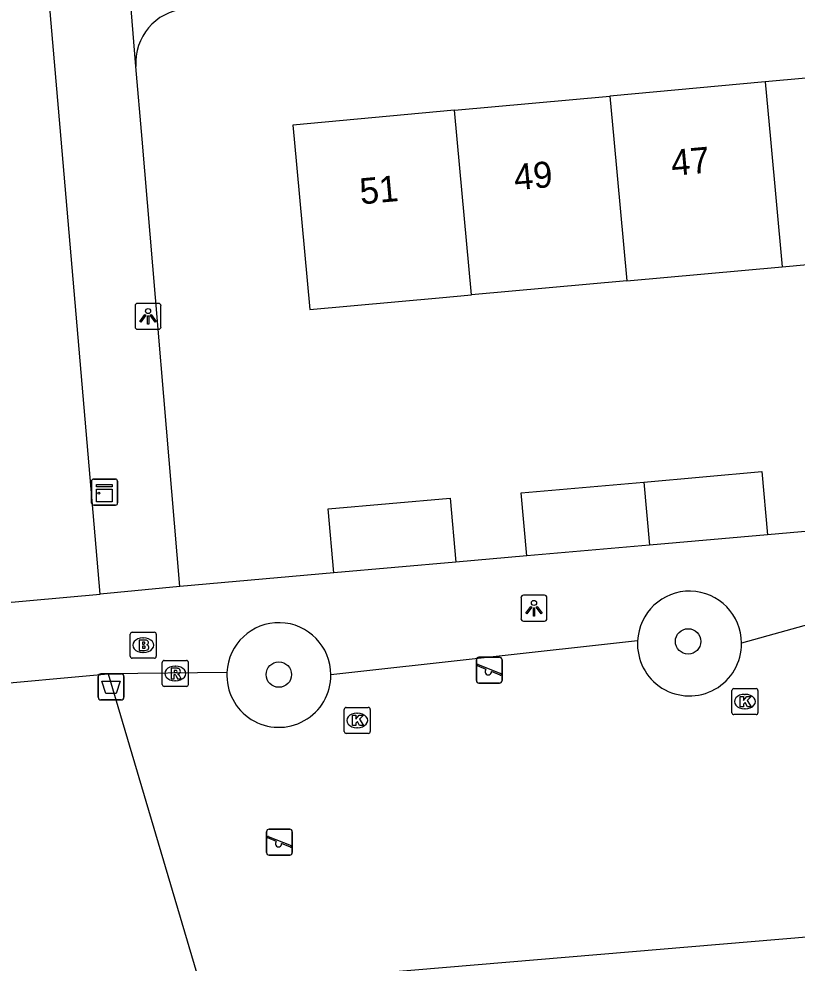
# Model space of a CAD drawing. Extents: x 160557 to 161245, y 385330 to 386505.
# Drawn here: x 160919.04 to 160948.98, y 385468.29 to 385504.63 of the extents above; entities that cross this region are included whole.
import ezdxf

# ---------------------------------------------------------------- set-up
doc = ezdxf.new("R2010")
doc.units = 0
for name, color, linetype in [('IMGEO_Afvalbak', 7, 'Continuous'), ('IMGEO_Boom', 7, 'Continuous'), ('IMGEO_Brandkraan', 7, 'Continuous'), ('IMGEO_Kast', 7, 'Continuous'), ('IMGEO_Kolk', 7, 'Continuous'), ('IMGEO_Lichtpunt', 7, 'Continuous'), ('IMGEO_Pand', 7, 'Continuous'), ('IMGEO_Pand_nummerreeks', 7, 'Continuous'), ('IMGEO_Rioolput', 7, 'Continuous'), ('IMGEO_Speelvoorziening', 7, 'Continuous'), ('IMGEO_Voetpad_open', 7, 'Continuous')]:
    doc.layers.add(name, color=color, linetype=linetype)

msp = doc.modelspace()

# ---------------------------------------------------------------- linework, layer by layer
at = {"layer": 'IMGEO_Afvalbak'}
for p, q in [((160922.086, 385478.522), (160922.086, 385479.322)), ((160922.086, 385479.322), (160922.086, 385478.522)), ((160922.186, 385479.422), (160922.976, 385479.422)), ((160922.976, 385479.422), (160922.186, 385479.422)), ((160923.076, 385479.322), (160923.076, 385478.522)), ((160923.076, 385478.522), (160923.076, 385479.322)), ((160922.976, 385478.422), (160922.186, 385478.422)), ((160922.186, 385478.422), (160922.976, 385478.422))]:
    msp.add_line(p, q, dxfattribs=at)
msp.add_lwpolyline([(160922.229, 385479.136), (160922.933, 385479.136), (160922.784, 385478.666), (160922.378, 385478.666), (160922.229, 385479.136)], dxfattribs=at)
for centre, start, end in [((160922.186, 385479.322), 90, 180), ((160922.186, 385479.322), 90, 180), ((160922.976, 385479.322), 0, 90), ((160922.976, 385479.322), 360, 90), ((160922.186, 385478.522), 180, 270), ((160922.186, 385478.522), 180, 270), ((160922.976, 385478.522), 270, 0), ((160922.976, 385478.522), 270, 0)]:
    msp.add_arc(centre, 0.1, start, end, dxfattribs=at)
at = {"layer": 'IMGEO_Boom'}
for centre in [(160944.785, 385480.673), (160929.039, 385479.396)]:
    msp.add_circle(centre, 0.489, dxfattribs=at)
at = {"layer": 'IMGEO_Brandkraan'}
for p, q in [((160923.321, 385480.099), (160923.321, 385480.951)), ((160923.396, 385481.025), (160924.248, 385481.025)), ((160923.809, 385480.805), (160923.834, 385480.805)), ((160924.322, 385480.951), (160924.322, 385480.099)), ((160923.832, 385480.245), (160923.807, 385480.245)), ((160924.248, 385480.025), (160923.396, 385480.025))]:
    msp.add_line(p, q, dxfattribs=at)
for points in [[(160923.321, 385480.099), (160923.321, 385480.951)], [(160923.396, 385481.025), (160924.248, 385481.025)], [(160924.322, 385480.951), (160924.322, 385480.099)], [(160923.669, 385480.725), (160923.669, 385480.325), (160923.882, 385480.325)], [(160923.9, 385480.725), (160923.669, 385480.725)], [(160923.848, 385480.644), (160923.794, 385480.644), (160923.794, 385480.568)], [(160923.794, 385480.568), (160923.847, 385480.568)], [(160923.856, 385480.492), (160923.794, 385480.492), (160923.794, 385480.411)], [(160923.794, 385480.411), (160923.856, 385480.411)], [(160924.248, 385480.025), (160923.396, 385480.025)]]:
    msp.add_lwpolyline(points, dxfattribs=at)
for centre, radius, start, end in [((160923.398, 385480.949), 0.0765, 91.552, 178.448), ((160923.398, 385480.949), 0.0765, 91.552, 178.448), ((160924.246, 385480.949), 0.0765, 1.552, 88.448), ((160924.246, 385480.949), 0.0765, 1.552, 88.448), ((160923.849, 385480.606), 0.0379, 267.8285, 90.9355), ((160923.857, 385480.451), 0.0404, 269.8759, 90.5077), ((160923.904, 385480.58), 0.145, 59.4692, 91.5367), ((160923.929, 385480.627), 0.0922, 285.5137, 58.1501), ((160923.934, 385480.435), 0.105, 301.3115, 78.989), ((160923.398, 385480.101), 0.0765, 181.552, 268.448), ((160923.398, 385480.101), 0.0765, 181.552, 268.448), ((160923.888, 385480.576), 0.251, 268.6676, 293.5347), ((160924.246, 385480.101), 0.0765, 271.552, 358.448), ((160924.246, 385480.101), 0.0765, 271.552, 358.448)]:
    msp.add_arc(centre, radius, start, end, dxfattribs=at)
for centre, major_axis, ratio, start_param, end_param in [((160923.808, 385480.525), (-0.387, 0.002), 0.722429, 4.712389, 7.853982), ((160923.833, 385480.525), (-0.39, 0.002), 0.717154, 1.570796, 4.712389)]:
    msp.add_ellipse(centre, major_axis=major_axis, ratio=ratio, start_param=start_param, end_param=end_param, dxfattribs=at)
at = {"layer": 'IMGEO_Kast'}
for p, q in [((160921.832, 385485.994), (160921.832, 385486.835)), ((160921.832, 385486.835), (160921.832, 385485.994)), ((160921.907, 385486.919), (160922.748, 385486.919)), ((160922.748, 385486.919), (160921.907, 385486.919)), ((160922.832, 385486.844), (160922.832, 385486.003)), ((160922.832, 385486.003), (160922.832, 385486.844)), ((160922.757, 385485.919), (160921.916, 385485.919)), ((160921.916, 385485.919), (160922.757, 385485.919))]:
    msp.add_line(p, q, dxfattribs=at)
for points in [[(160922.027, 385486.709), (160922.627, 385486.709), (160922.627, 385486.624), (160922.027, 385486.624), (160922.027, 385486.709)], [(160922.027, 385486.534), (160922.627, 385486.534), (160922.627, 385486.045), (160922.027, 385486.045), (160922.027, 385486.534)]]:
    msp.add_lwpolyline(points, dxfattribs=at)
msp.add_circle((160922.111, 385486.383), 0.0377, dxfattribs=at)
for centre, start, end in [((160921.91, 385486.841), 92.4484, 184.2845), ((160921.91, 385486.841), 92.4484, 184.2845), ((160922.754, 385486.841), 2.4484, 94.2845), ((160922.754, 385486.841), 2.4484, 94.2845), ((160921.91, 385485.997), 182.4484, 274.2845), ((160921.91, 385485.997), 182.4484, 274.2845), ((160922.754, 385485.997), 272.4484, 4.2845), ((160922.754, 385485.997), 272.4484, 4.2845)]:
    msp.add_arc(centre, 0.0779, start, end, dxfattribs=at)
at = {"layer": 'IMGEO_Kolk'}
for p, q in [((160946.471, 385477.929), (160946.471, 385478.781)), ((160946.546, 385478.855), (160947.398, 385478.855)), ((160946.959, 385478.635), (160946.984, 385478.635)), ((160947.472, 385478.781), (160947.472, 385477.929)), ((160931.554, 385477.204), (160931.554, 385478.056)), ((160931.629, 385478.13), (160932.481, 385478.13)), ((160932.042, 385477.91), (160932.067, 385477.91)), ((160932.555, 385478.056), (160932.555, 385477.204)), ((160946.982, 385478.075), (160946.957, 385478.075)), ((160947.398, 385477.855), (160946.546, 385477.855)), ((160932.065, 385477.35), (160932.04, 385477.35)), ((160932.481, 385477.13), (160931.629, 385477.13))]:
    msp.add_line(p, q, dxfattribs=at)
for points in [[(160946.471, 385477.929), (160946.471, 385478.781)], [(160946.546, 385478.855), (160947.398, 385478.855)], [(160947.472, 385478.781), (160947.472, 385477.929)], [(160946.792, 385478.555), (160946.915, 385478.555), (160946.915, 385478.404), (160947.045, 385478.555), (160947.209, 385478.555), (160947.063, 385478.404), (160947.216, 385478.155), (160947.064, 385478.155), (160946.979, 385478.319), (160946.915, 385478.252), (160946.915, 385478.155), (160946.792, 385478.155), (160946.792, 385478.555)], [(160931.554, 385477.204), (160931.554, 385478.056)], [(160931.629, 385478.13), (160932.481, 385478.13)], [(160932.555, 385478.056), (160932.555, 385477.204)], [(160931.875, 385477.83), (160931.998, 385477.83), (160931.998, 385477.679), (160932.128, 385477.83), (160932.292, 385477.83), (160932.146, 385477.679), (160932.299, 385477.43), (160932.147, 385477.43), (160932.062, 385477.594), (160931.998, 385477.527), (160931.998, 385477.43), (160931.875, 385477.43), (160931.875, 385477.83)], [(160947.398, 385477.855), (160946.546, 385477.855)], [(160932.481, 385477.13), (160931.629, 385477.13)]]:
    msp.add_lwpolyline(points, dxfattribs=at)
for centre, start, end in [((160946.548, 385478.779), 91.552, 178.448), ((160946.548, 385478.779), 91.552, 178.448), ((160947.396, 385478.779), 1.552, 88.448), ((160947.396, 385478.779), 1.552, 88.448), ((160931.631, 385478.054), 91.552, 178.448), ((160931.631, 385478.054), 91.552, 178.448), ((160932.479, 385478.054), 1.552, 88.448), ((160932.479, 385478.054), 1.552, 88.448), ((160946.548, 385477.931), 181.552, 268.448), ((160946.548, 385477.931), 181.552, 268.448), ((160947.396, 385477.931), 271.552, 358.448), ((160947.396, 385477.931), 271.552, 358.448), ((160931.631, 385477.206), 181.552, 268.448), ((160931.631, 385477.206), 181.552, 268.448), ((160932.479, 385477.206), 271.552, 358.448), ((160932.479, 385477.206), 271.552, 358.448)]:
    msp.add_arc(centre, 0.0765, start, end, dxfattribs=at)
for centre, major_axis, ratio, start_param, end_param in [((160946.958, 385478.355), (-0.387, 0.002), 0.722429, 4.712389, 7.853982), ((160946.983, 385478.355), (-0.39, 0.002), 0.717154, 1.570796, 4.712389), ((160932.041, 385477.63), (-0.387, 0.002), 0.722429, 4.712389, 7.853982), ((160932.066, 385477.63), (-0.39, 0.002), 0.717154, 1.570796, 4.712389)]:
    msp.add_ellipse(centre, major_axis=major_axis, ratio=ratio, start_param=start_param, end_param=end_param, dxfattribs=at)
at = {"layer": 'IMGEO_Lichtpunt'}
for p, q in [((160923.508, 385493.589), (160923.508, 385492.782)), ((160923.508, 385493.589), (160923.508, 385492.782)), ((160924.41, 385493.684), (160923.602, 385493.684)), ((160924.41, 385493.684), (160923.602, 385493.684)), ((160924.504, 385492.782), (160924.504, 385493.589)), ((160924.504, 385492.782), (160924.504, 385493.589)), ((160923.602, 385492.688), (160924.41, 385492.688)), ((160923.602, 385492.688), (160924.41, 385492.688)), ((160938.356, 385482.355), (160938.356, 385481.548)), ((160938.356, 385482.355), (160938.356, 385481.548)), ((160939.258, 385482.45), (160938.45, 385482.45)), ((160939.258, 385482.45), (160938.45, 385482.45)), ((160939.352, 385481.548), (160939.352, 385482.355)), ((160939.352, 385481.548), (160939.352, 385482.355)), ((160938.45, 385481.454), (160939.258, 385481.454)), ((160938.45, 385481.454), (160939.258, 385481.454))]:
    msp.add_line(p, q, dxfattribs=at)
for points in [[(160923.882, 385493.253), (160923.921, 385493.225), (160923.733, 385492.963), (160923.695, 385492.99), (160923.882, 385493.253)], [(160923.984, 385493.205), (160924.031, 385493.205), (160924.031, 385492.883), (160923.984, 385492.883), (160923.984, 385493.205)], [(160924.094, 385493.225), (160924.132, 385493.252), (160924.319, 385492.99), (160924.28, 385492.962), (160924.094, 385493.225)], [(160938.73, 385482.019), (160938.769, 385481.991), (160938.581, 385481.729), (160938.543, 385481.756), (160938.73, 385482.019)], [(160938.832, 385481.971), (160938.879, 385481.971), (160938.879, 385481.649), (160938.832, 385481.649), (160938.832, 385481.971)], [(160938.942, 385481.991), (160938.98, 385482.018), (160939.167, 385481.756), (160939.128, 385481.728), (160938.942, 385481.991)]]:
    msp.add_lwpolyline(points, dxfattribs=at)
for centre in [(160924.007, 385493.387), (160938.855, 385482.153)]:
    msp.add_circle(centre, 0.0994, dxfattribs=at)
for centre, start, end in [((160923.602, 385493.589), 90, 180), ((160923.602, 385493.589), 90, 180), ((160924.41, 385493.589), 0, 90), ((160924.41, 385493.589), 0, 90), ((160923.602, 385492.782), 180, 270), ((160923.602, 385492.782), 180, 270), ((160924.41, 385492.782), 270, 0), ((160924.41, 385492.782), 270, 360), ((160938.45, 385482.355), 90, 180), ((160938.45, 385482.355), 90, 180), ((160939.258, 385482.355), 0, 90), ((160939.258, 385482.355), 0, 90), ((160938.45, 385481.548), 180, 270), ((160938.45, 385481.548), 180, 270), ((160939.258, 385481.548), 270, 0), ((160939.258, 385481.548), 270, 360)]:
    msp.add_arc(centre, 0.0946, start, end, dxfattribs=at)
at = {"layer": 'IMGEO_Pand'}
for points in [[(160953.725, 385502.756), (160947.749, 385502.209)], [(160947.749, 385502.209), (160941.774, 385501.662)], [(160947.749, 385502.209), (160947.951, 385500), (160948.4, 385495.096)], [(160935.799, 385501.116), (160941.774, 385501.662)], [(160941.774, 385501.662), (160941.926, 385500), (160942.425, 385494.554)], [(160935.799, 385501.116), (160929.582, 385500.547), (160929.632, 385500), (160930.227, 385493.449), (160935.207, 385493.9), (160936.449, 385494.013)], [(160936.449, 385494.013), (160935.901, 385500), (160935.799, 385501.116)], [(160948.4, 385495.096), (160954.377, 385495.638)], [(160942.425, 385494.554), (160948.4, 385495.096)], [(160942.425, 385494.554), (160936.449, 385494.013)], [(160943.083, 385486.806), (160947.62, 385487.206), (160947.834, 385484.777)], [(160938.58, 385483.961), (160938.366, 385486.39), (160943.083, 385486.806)], [(160943.083, 385486.806), (160943.305, 385484.378)], [(160931.149, 385483.306), (160930.931, 385485.774), (160935.634, 385486.189), (160935.852, 385483.721)], [(160947.834, 385484.777), (160943.305, 385484.378)], [(160943.305, 385484.378), (160938.58, 385483.961)], [(160935.852, 385483.721), (160931.149, 385483.306)]]:
    msp.add_lwpolyline(points, dxfattribs=at)
at = {"layer": 'IMGEO_Rioolput'}
for p, q in [((160924.555, 385479.012), (160924.555, 385479.864)), ((160924.63, 385479.938), (160925.482, 385479.938)), ((160925.043, 385479.718), (160925.068, 385479.718)), ((160925.556, 385479.864), (160925.556, 385479.012)), ((160925.066, 385479.158), (160925.041, 385479.158)), ((160925.482, 385478.938), (160924.63, 385478.938))]:
    msp.add_line(p, q, dxfattribs=at)
for points in [[(160924.555, 385479.012), (160924.555, 385479.864)], [(160924.63, 385479.938), (160925.482, 385479.938)], [(160925.556, 385479.864), (160925.556, 385479.012)], [(160925.144, 385479.636), (160924.892, 385479.638), (160924.892, 385479.238)], [(160924.892, 385479.238), (160925.016, 385479.238), (160925.016, 385479.4), (160925.027, 385479.4)], [(160925.07, 385479.557), (160925.016, 385479.557), (160925.016, 385479.476)], [(160925.016, 385479.476), (160925.068, 385479.476)], [(160925.074, 385479.371), (160925.145, 385479.238), (160925.285, 385479.238), (160925.22, 385479.364)], [(160925.482, 385478.938), (160924.63, 385478.938)]]:
    msp.add_lwpolyline(points, dxfattribs=at)
for centre, radius, start, end in [((160924.632, 385479.862), 0.0765, 91.552, 178.448), ((160924.632, 385479.862), 0.0765, 91.552, 178.448), ((160925.48, 385479.862), 0.0765, 1.552, 88.448), ((160925.48, 385479.862), 0.0765, 1.552, 88.448), ((160925.026, 385479.347), 0.0533, 26.0293, 88.6989), ((160925.052, 385479.665), 0.19, 274.7715, 282.9687), ((160925.076, 385479.461), 0.0964, 77.0061, 93.1865), ((160925.09, 385479.518), 0.0378, 276.6634, 79.6772), ((160925.143, 385479.526), 0.109, 350.3612, 89.416), ((160925.141, 385479.526), 0.112, 277.5842, 350.9817), ((160925.125, 385479.311), 0.108, 29.5134, 73.7905), ((160924.632, 385479.014), 0.0765, 181.552, 268.448), ((160924.632, 385479.014), 0.0765, 181.552, 268.448), ((160925.48, 385479.014), 0.0765, 271.552, 358.448), ((160925.48, 385479.014), 0.0765, 271.552, 358.448)]:
    msp.add_arc(centre, radius, start, end, dxfattribs=at)
for centre, major_axis, ratio, start_param, end_param in [((160925.042, 385479.438), (-0.387, 0.002), 0.722429, 4.712389, 7.853982), ((160925.067, 385479.438), (-0.39, 0.002), 0.717154, 1.570796, 4.712389)]:
    msp.add_ellipse(centre, major_axis=major_axis, ratio=ratio, start_param=start_param, end_param=end_param, dxfattribs=at)
at = {"layer": 'IMGEO_Speelvoorziening'}
for p, q in [((160936.738, 385480.064), (160937.528, 385480.064)), ((160937.528, 385480.064), (160936.738, 385480.064)), ((160936.638, 385479.164), (160936.638, 385479.964)), ((160936.638, 385479.964), (160936.638, 385479.164)), ((160937.021, 385479.592), (160936.682, 385479.729)), ((160936.707, 385479.789), (160937.583, 385479.436)), ((160937.628, 385479.964), (160937.628, 385479.164)), ((160937.628, 385479.164), (160937.628, 385479.964)), ((160937.559, 385479.376), (160937.219, 385479.513)), ((160937.528, 385479.064), (160936.738, 385479.064)), ((160936.738, 385479.064), (160937.528, 385479.064)), ((160928.565, 385472.544), (160928.565, 385473.344)), ((160928.565, 385473.344), (160928.565, 385472.544)), ((160928.634, 385473.169), (160929.51, 385472.816)), ((160928.665, 385473.444), (160929.455, 385473.444)), ((160929.455, 385473.444), (160928.665, 385473.444)), ((160929.555, 385473.344), (160929.555, 385472.544)), ((160929.555, 385472.544), (160929.555, 385473.344)), ((160928.948, 385472.972), (160928.609, 385473.109)), ((160929.486, 385472.756), (160929.146, 385472.893)), ((160929.455, 385472.444), (160928.665, 385472.444)), ((160928.665, 385472.444), (160929.455, 385472.444))]:
    msp.add_line(p, q, dxfattribs=at)
for centre, radius, start, end in [((160936.738, 385479.964), 0.1, 90, 180), ((160936.738, 385479.964), 0.1, 90, 180), ((160937.528, 385479.964), 0.1, 0, 90), ((160937.528, 385479.964), 0.1, 360, 90), ((160936.695, 385479.759), 0.0327, 68.078, 248.078), ((160937.1, 385479.502), 0.12, 130.9928, 5.1632), ((160937.571, 385479.406), 0.0327, 248.078, 68.078), ((160936.738, 385479.164), 0.1, 180, 270), ((160936.738, 385479.164), 0.1, 180, 270), ((160937.528, 385479.164), 0.1, 270, 0), ((160937.528, 385479.164), 0.1, 270, 0), ((160928.665, 385473.344), 0.1, 90, 180), ((160928.665, 385473.344), 0.1, 90, 180), ((160928.622, 385473.139), 0.0327, 68.078, 248.078), ((160929.455, 385473.344), 0.1, 0, 90), ((160929.455, 385473.344), 0.1, 360, 90), ((160929.027, 385472.882), 0.12, 130.9928, 5.1632), ((160929.498, 385472.786), 0.0327, 248.078, 68.078), ((160928.665, 385472.544), 0.1, 180, 270), ((160928.665, 385472.544), 0.1, 180, 270), ((160929.455, 385472.544), 0.1, 270, 0), ((160929.455, 385472.544), 0.1, 270, 0)]:
    msp.add_arc(centre, radius, start, end, dxfattribs=at)
at = {"layer": 'IMGEO_Voetpad_open'}
for points in [[(160922.169, 385482.49), (160920.66, 385500), (160917.04, 385541.995)], [(160923.539, 385502.802), (160922.751, 385512.494)], [(160925.231, 385482.784), (160923.776, 385500), (160923.539, 385502.802)], [(160950.596, 385485.021), (160947.834, 385484.777)], [(160938.58, 385483.961), (160935.852, 385483.721)], [(160931.149, 385483.306), (160925.231, 385482.784)], [(160956.058, 385483.167), (160946.836, 385480.602)], [(160925.231, 385482.784), (160922.169, 385482.49)], [(160900.653, 385480.551), (160900.782, 385480.563), (160922.169, 385482.49)], [(160942.842, 385480.689), (160931.036, 385479.388)], [(160874.775, 385475.11), (160917.394, 385478.959), (160922.473, 385479.418)], [(160927.044, 385479.479), (160922.473, 385479.418)], [(160922.473, 385479.418), (160926.05, 385467.331)], [(160951.932, 385469.506), (160926.05, 385467.331)]]:
    msp.add_lwpolyline(points, dxfattribs=at)
for centre, radius, start, end in [((160925.613, 385502.949), 2.079, 95.621, 184.0595), ((160944.838, 385480.609), 1.998, 359.8065, 177.6978), ((160929.039, 385479.396), 1.997, 359.7779, 177.6104), ((160944.837, 385480.574), 1.999, 176.6903, 0.814), ((160929.038, 385479.363), 1.998, 176.6606, 0.7277)]:
    msp.add_arc(centre, radius, start, end, dxfattribs=at)

# ---------------------------------------------------------------- texts
at = {"layer": 'IMGEO_Pand_nummerreeks'}
for s, p in [('47', (160944.171, 385498.588)), ('49', (160938.126, 385498.035)), ('51', (160932.193, 385497.492))]:
    msp.add_text(s, height=1, rotation=5.2269, dxfattribs=at).set_placement(p)

doc.saveas('drawing.dxf')
